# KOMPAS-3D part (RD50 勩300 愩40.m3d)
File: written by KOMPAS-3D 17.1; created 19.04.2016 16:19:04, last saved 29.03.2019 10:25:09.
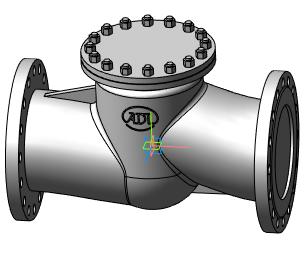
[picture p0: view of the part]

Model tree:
1. Операция без истории:2  (labels: Сталь 20  ГОСТ 1050-88)

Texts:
  RD50 Ду15 Ру40
  RD50 Ду20 Ру40
  RD50 Ду25 Ру40
  RD50 Ду32 Ру40
  RD50 Ду40 Ру40
  RD50 Ду50 Ру40
  RD50 Ду65 Ру40
  RD50 Ду80 Ру40
  RD50 Ду100 Ру40
  RD50 Ду125 Ру40
  RD50 Ду150 Ру40
  RD50 Ду200 Ру40
  RD50 Ду250 Ру40
  RD50 Ду300 Ру40
  RD50 Ду350 Ру40
  RD50 Ду400 Ру40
